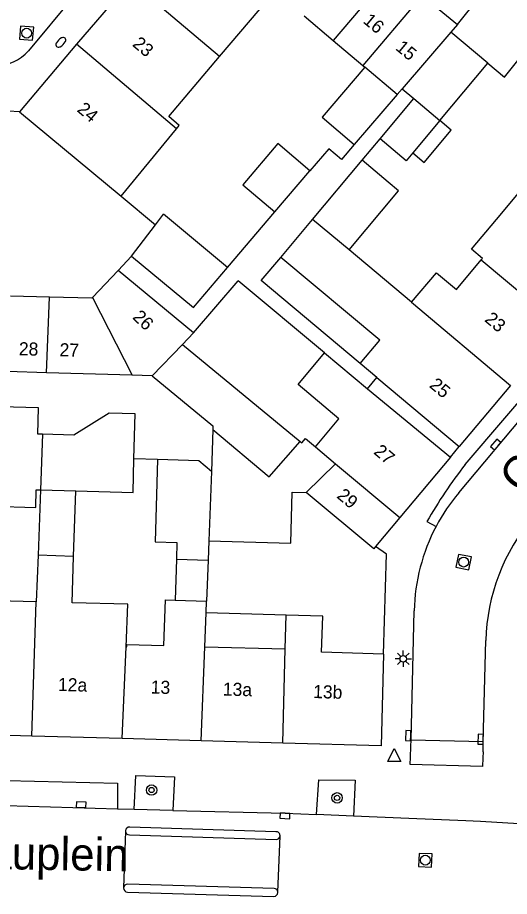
# Model space of a CAD drawing. Extents: x 132573 to 132944, y 398226 to 398676.
# Drawn here: x 132872.8 to 132910.4, y 398274.7 to 398341.8 of the extents above; entities that cross this region are included whole.
import ezdxf

# ---------------------------------------------------------------- set-up
doc = ezdxf.new("R2010")
doc.units = 0
for name, color, linetype in [('gg-afsc-erfafscheiding', 7, 'Continuous'), ('gg-afsc-muur', 7, 'Continuous'), ('gg-anno-huisnummerreeks BGT', 7, 'Continuous'), ('gg-anno-openbare ruimte label', 7, 'Continuous'), ('gg-bbg-bijgebouw', 7, 'Continuous'), ('gg-bbg-gedigitaliseerde bebouwing', 7, 'Continuous'), ('gg-bbg-gedigitaliseerde bebouwing onder overbouw', 7, 'Continuous'), ('gg-bbg-gedigitaliseerde bijgebouw', 7, 'Continuous'), ('gg-bbg-gedigitaliseerde overbouw', 7, 'Continuous'), ('gg-bbg-hoofdgebouw', 7, 'Continuous'), ('gg-bbg-luifel en loopbrug', 7, 'Continuous'), ('gg-bbg-pand overbouw', 7, 'Continuous'), ('gg-bbg-tussenscheiding', 7, 'Continuous'), ('gg-knt-verharding', 7, 'Continuous'), ('gg-knt-verharding nz', 7, 'Continuous'), ('gt-symb-boom', 7, 'Continuous'), ('gt-symb-brandkraan', 7, 'Continuous'), ('gt-symb-kolk', 7, 'Continuous'), ('gt-symb-lichtmast', 7, 'Continuous'), ('gt-symb-rioolschacht', 7, 'Continuous'), ('gt-symb-waterafsluiter', 7, 'Continuous')]:
    doc.layers.add(name, color=color, linetype=linetype)

msp = doc.modelspace()

# ---------------------------------------------------------------- linework, layer by layer
at = {"layer": 'gg-afsc-erfafscheiding'}
for p, q in [((132899.138, 398330.927), (132900.51, 398332.564)), ((132888.86, 398322.738), (132892.469, 398326.97)), ((132886.266, 398317.726), (132889.671, 398321.72)), ((132896.261, 398316.198), (132889.671, 398321.72)), ((132883.514, 398308.056), (132881.705, 398308.103))]:
    msp.add_line(p, q, dxfattribs=at)
for points in [[(132898.536, 398332.137), (132897.558, 398330.97), (132896.583, 398331.795), (132895.152, 398330.117)], [(132898.992, 398315.392), (132891.43, 398321.729), (132892.917, 398323.503)]]:
    msp.add_lwpolyline(points, dxfattribs=at)
at = {"layer": 'gg-afsc-muur'}
msp.add_line((132880.732, 398328.18), (132883.355, 398325.989), dxfattribs=at)
msp.add_lwpolyline([(132900.78, 398293.185), (132900.99, 398300.82), (132900.167, 398301.416)], dxfattribs=at)
at = {"layer": 'gg-bbg-bijgebouw'}
for p, q in [((132906.42, 398341.29), (132910.388, 398346.238)), ((132903.731, 398343.519), (132906.42, 398341.29)), ((132883.355, 398325.989), (132883.966, 398326.793)), ((132881.526, 398323.584), (132883.355, 398325.989)), ((132880.503, 398322.5), (132878.549, 398320.448)), ((132886.266, 398317.726), (132880.503, 398322.5)), ((132875.263, 398320.47), (132872.269, 398320.548)), ((132902.02, 398303.628), (132900.167, 398301.416)), ((132900.167, 398301.416), (132900.02, 398301.24))]:
    msp.add_line(p, q, dxfattribs=at)
msp.add_lwpolyline([(132878.549, 398320.448), (132878.489, 398320.385), (132875.263, 398320.47)], dxfattribs=at)
at = {"layer": 'gg-bbg-gedigitaliseerde bebouwing'}
for p, q in [((132888.246, 398338.849), (132892.476, 398343.845)), ((132884.952, 398333.331), (132885.164, 398333.59)), ((132880.732, 398328.18), (132884.952, 398333.331)), ((132909.405, 398326.405), (132911.337, 398328.711)), ((132892.917, 398323.503), (132895.351, 398326.407)), ((132902.912, 398320.07), (132898.136, 398324.072)), ((132900.479, 398317.166), (132892.917, 398323.503)), ((132898.992, 398315.392), (132900.479, 398317.166)), ((132896.261, 398316.198), (132899.536, 398313.454)), ((132900.265, 398314.324), (132898.992, 398315.392)), ((132895.577, 398309.027), (132897.37, 398311.167)), ((132874.392, 398300.75), (132874.234, 398297.191)), ((132877.095, 398300.661), (132874.392, 398300.75)), ((132874.234, 398297.191), (132867.226, 398297.386)), ((132884.866, 398297.314), (132887.25, 398297.248)), ((132887.216, 398296.355), (132887.25, 398297.248)), ((132887.117, 398293.758), (132887.216, 398296.355)), ((132893.255, 398293.592), (132893.324, 398296.168)), ((132887.117, 398293.758), (132893.255, 398293.592))]:
    msp.add_line(p, q, dxfattribs=at)
for points in [[(132885.164, 398333.59), (132884.366, 398334.265), (132888.246, 398338.849)], [(132908.23, 398323.307), (132908.33, 398323.426), (132907.495, 398324.126), (132909.405, 398326.405)], [(132902.912, 398320.07), (132904.806, 398322.33), (132906.337, 398321.047), (132908.23, 398323.307)], [(132897.37, 398311.167), (132894.242, 398313.788), (132896.261, 398316.198)], [(132881.104, 398293.735), (132881.241, 398296.997), (132876.977, 398297.101), (132877.095, 398300.661)], [(132883.984, 398293.843), (132884.117, 398297.335), (132884.866, 398297.314)], [(132881.104, 398293.735), (132881.151, 398293.734), (132881.156, 398293.919), (132883.984, 398293.843)]]:
    msp.add_lwpolyline(points, dxfattribs=at)
at = {"layer": 'gg-bbg-gedigitaliseerde bebouwing onder overbouw'}
for p, q in [((132900.265, 398314.324), (132906.562, 398309.046)), ((132899.536, 398313.454), (132905.882, 398308.235))]:
    msp.add_line(p, q, dxfattribs=at)
at = {"layer": 'gg-bbg-gedigitaliseerde bijgebouw'}
for p, q in [((132910.008, 398337.28), (132914.457, 398342.827)), ((132894.719, 398341.948), (132896.932, 398340.075)), ((132896.932, 398340.075), (132899.196, 398338.16)), ((132905.075, 398333.957), (132908.746, 398338.337)), ((132908.746, 398338.337), (132910.008, 398337.28)), ((132899.196, 398338.16), (132899.333, 398338.044)), ((132902.187, 398336.376), (132901.816, 398335.945)), ((132902.187, 398336.376), (132903.078, 398335.629)), ((132901.816, 398335.945), (132898.536, 398332.137)), ((132900.51, 398332.564), (132903.078, 398335.629)), ((132905.075, 398333.957), (132903, 398331.481)), ((132895.351, 398326.407), (132899.138, 398330.927)), ((132901.134, 398329.254), (132899.138, 398330.927)), ((132892.469, 398326.97), (132895.152, 398330.117)), ((132888.86, 398322.738), (132883.966, 398326.793)), ((132881.526, 398323.584), (132886.249, 398319.675)), ((132886.249, 398319.675), (132888.86, 398322.738)), ((132886.266, 398317.726), (132885.404, 398316.836)), ((132885.404, 398316.836), (132894.398, 398309.429)), ((132875.037, 398314.69), (132872.043, 398314.777)), ((132881.567, 398314.502), (132875.037, 398314.69)), ((132883.1, 398314.458), (132881.567, 398314.502)), ((132887.73, 398310.354), (132887.63, 398307.149)), ((132874.564, 398305.744), (132877.261, 398305.669)), ((132900.02, 398301.24), (132894.861, 398305.539)), ((132887.426, 398301.844), (132887.37, 398300.373)), ((132884.953, 398300.44), (132887.37, 398300.373))]:
    msp.add_line(p, q, dxfattribs=at)
for points in [[(132899.333, 398338.044), (132896.085, 398334.217), (132898.536, 398332.137)], [(132895.152, 398330.117), (132892.703, 398332.205), (132890.012, 398329.049), (132892.469, 398326.97)], [(132903, 398331.481), (132902.506, 398330.891), (132900.51, 398332.564)], [(132898.136, 398324.072), (132901.924, 398328.592), (132901.134, 398329.254)], [(132883.1, 398314.458), (132887.738, 398310.639), (132887.73, 398310.354)], [(132874.711, 398309.991), (132874.355, 398310.001), (132874.411, 398312.001), (132867.666, 398312.188)], [(132881.705, 398308.103), (132881.801, 398311.545), (132879.802, 398311.601), (132877.104, 398309.925), (132874.711, 398309.991)], [(132894.398, 398309.429), (132894.526, 398309.324), (132894.805, 398309.663), (132895.577, 398309.027)], [(132877.261, 398305.669), (132881.634, 398305.547), (132881.705, 398308.103)], [(132883.514, 398308.056), (132883.339, 398301.758), (132884.988, 398301.712), (132884.953, 398300.44)], [(132887.63, 398307.149), (132886.663, 398307.968), (132883.514, 398308.056)], [(132867.52, 398307.291), (132867.577, 398307.289), (132867.502, 398304.59), (132874.199, 398304.404), (132874.237, 398305.753), (132874.564, 398305.744)], [(132887.426, 398301.844), (132893.691, 398301.67), (132893.799, 398305.569), (132894.861, 398305.539)]]:
    msp.add_lwpolyline(points, dxfattribs=at)
at = {"layer": 'gg-bbg-gedigitaliseerde overbouw'}
msp.add_line((132899.536, 398313.454), (132900.265, 398314.324), dxfattribs=at)
at = {"layer": 'gg-bbg-hoofdgebouw'}
for p, q in [((132881.424, 398344.622), (132877.328, 398339.782)), ((132877.328, 398339.782), (132872.96, 398334.62)), ((132872.96, 398334.62), (132880.732, 398328.18)), ((132910.483, 398313.725), (132906.562, 398309.046)), ((132905.882, 398308.235), (132902.02, 398303.628)), ((132900.78, 398293.185), (132900.6, 398286.19)), ((132873.916, 398286.932), (132871.073, 398287.011)), ((132880.809, 398286.741), (132873.916, 398286.932)), ((132886.841, 398286.573), (132880.809, 398286.741)), ((132893.074, 398286.399), (132886.841, 398286.573)), ((132900.6, 398286.19), (132893.074, 398286.399))]:
    msp.add_line(p, q, dxfattribs=at)
msp.add_lwpolyline([(132900.78, 398293.185), (132896.031, 398293.33), (132896.139, 398296.082), (132893.324, 398296.168)], dxfattribs=at)
at = {"layer": 'gg-bbg-luifel en loopbrug'}
for p, q in [((132874.564, 398305.744), (132874.392, 398300.75)), ((132877.095, 398300.661), (132877.261, 398305.669)), ((132884.953, 398300.44), (132884.866, 398297.314)), ((132887.37, 398300.373), (132887.25, 398297.248)), ((132893.324, 398296.168), (132887.216, 398296.355))]:
    msp.add_line(p, q, dxfattribs=at)
msp.add_lwpolyline([(132903, 398331.481), (132903.865, 398330.757), (132905.94, 398333.233), (132905.075, 398333.957)], dxfattribs=at)
at = {"layer": 'gg-bbg-pand overbouw'}
msp.add_line((132905.882, 398308.235), (132906.562, 398309.046), dxfattribs=at)
at = {"layer": 'gg-bbg-tussenscheiding'}
for p, q in [((132901.448, 398345.411), (132896.932, 398340.075)), ((132888.246, 398338.849), (132881.424, 398344.622)), ((132903.731, 398343.519), (132899.196, 398338.16)), ((132906.42, 398341.29), (132905.918, 398340.707)), ((132905.918, 398340.707), (132902.187, 398336.376)), ((132908.746, 398338.337), (132905.918, 398340.707)), ((132884.952, 398333.331), (132877.328, 398339.782)), ((132901.816, 398335.945), (132899.333, 398338.044)), ((132903.078, 398335.629), (132905.075, 398333.957)), ((132898.136, 398324.072), (132895.351, 398326.407)), ((132908.23, 398323.307), (132914.27, 398318.244)), ((132875.037, 398314.69), (132875.263, 398320.47)), ((132878.549, 398320.448), (132881.567, 398314.502)), ((132902.912, 398320.07), (132910.483, 398313.725)), ((132883.1, 398314.458), (132885.404, 398316.836)), ((132874.711, 398309.991), (132874.564, 398305.744)), ((132895.577, 398309.027), (132897.113, 398307.74)), ((132894.861, 398305.539), (132897.113, 398307.74)), ((132897.113, 398307.74), (132902.02, 398303.628)), ((132887.63, 398307.149), (132887.426, 398301.844)), ((132873.916, 398286.932), (132874.234, 398297.191)), ((132880.809, 398286.741), (132881.104, 398293.735)), ((132886.841, 398286.573), (132887.117, 398293.758)), ((132893.074, 398286.399), (132893.255, 398293.592))]:
    msp.add_line(p, q, dxfattribs=at)
msp.add_lwpolyline([(132887.73, 398310.354), (132892.028, 398306.74), (132894.398, 398309.429)], dxfattribs=at)
at = {"layer": 'gg-knt-verharding'}
for p, q in [((132881.896, 398349.211), (132873.641, 398339.288)), ((132872.96, 398334.62), (132867.14, 398335.01)), ((132880.503, 398322.5), (132881.526, 398323.584)), ((132906.52, 398305.52), (132920.22, 398321.839)), ((132902.875, 398286.651), (132903.109, 398296.502)), ((132908.396, 398286.505), (132908.58, 398294.222)), ((132902.862, 398286.128), (132902.875, 398286.651)), ((132902.875, 398286.651), (132908.396, 398286.505)), ((132908.378, 398285.735), (132908.396, 398286.505)), ((132902.843, 398285.326), (132902.862, 398286.128)), ((132902.798, 398284.756), (132902.843, 398285.326)), ((132908.361, 398285.275), (132908.337, 398284.61)), ((132908.378, 398285.735), (132908.361, 398285.275)), ((132908.337, 398284.61), (132902.798, 398284.756)), ((132880.446, 398281.347), (132871.917, 398281.588)), ((132881.719, 398281.311), (132880.446, 398281.347)), ((132884.68, 398281.235), (132881.719, 398281.311)), ((132898.475, 398280.804), (132895.661, 398280.927)), ((132902.701, 398280.632), (132898.475, 398280.804)), ((132892.557, 398279.624), (132881.379, 398279.97)), ((132914.016, 398280.052), (132908.181, 398280.39)), ((132881.057, 398279.666), (132880.918, 398275.328)), ((132881.058, 398279.7), (132881.057, 398279.666)), ((132881.356, 398279.376), (132892.559, 398279.019)), ((132892.696, 398274.991), (132892.864, 398279.3)), ((132892.864, 398279.3), (132892.865, 398279.319)), ((132892.412, 398275.292), (132881.237, 398275.62)), ((132881.21, 398275.007), (132892.396, 398274.677)), ((132892.695, 398274.965), (132892.696, 398274.991))]:
    msp.add_line(p, q, dxfattribs=at)
for points in [[(132881.719, 398281.311), (132881.855, 398283.904), (132884.814, 398283.818), (132884.68, 398281.235)], [(132871.917, 398281.588), (132871.992, 398283.526), (132880.446, 398283.338), (132880.446, 398281.347)], [(132895.661, 398280.927), (132895.828, 398283.595), (132898.615, 398283.562), (132898.475, 398280.804)], [(132884.68, 398281.235), (132893.246, 398281.033), (132895.661, 398280.927)], [(132908.181, 398280.39), (132907.058, 398280.455), (132902.701, 398280.632)]]:
    msp.add_lwpolyline(points, dxfattribs=at)
for centre, radius, start, end in [((132871.199, 398341.418), 3.241, 268.22036, 318.90359), ((132917.651, 398296.157), 14.545, 139.93235, 152.16455), ((132923.867, 398293.772), 15.294, 140.00224, 178.31374), ((132917.653, 398296.154), 14.548, 152.1579, 178.63074), ((132881.355, 398279.673), 0.298, 85.36573, 174.77009), ((132881.354, 398279.673), 0.297, 181.37149, 270.37935), ((132892.561, 398279.32), 0.304, 359.7889, 90.7719), ((132892.562, 398279.322), 0.303, 269.45359, 355.85586), ((132881.227, 398275.311), 0.309, 88.09534, 176.84417), ((132881.225, 398275.314), 0.308, 177.44441, 267.13849), ((132892.387, 398274.984), 0.309, 1.25813, 85.41279), ((132892.389, 398274.983), 0.307, 271.30695, 356.54593)]:
    msp.add_arc(centre, radius, start, end, dxfattribs=at)
at = {"layer": 'gg-knt-verharding nz'}
msp.add_line((132904.081, 398303.322), (132904.789, 398302.949), dxfattribs=at)
msp.add_lwpolyline([(132907.015, 398307.688), (132919.585, 398322.372), (132920.22, 398321.839)], dxfattribs=at)
msp.add_arc((132937.461, 398284.059), 38.539, 142.18521, 150.01172, dxfattribs=at)
at = {"layer": 'gt-symb-boom'}
for centre, radius in [((132883.052, 398282.805), 0.4), ((132883.052, 398282.805), 0.2), ((132897.222, 398282.207), 0.4), ((132897.222, 398282.207), 0.2)]:
    msp.add_circle(centre, radius, dxfattribs=at)
at = {"layer": 'gt-symb-brandkraan'}
for centre, radius, start, end in [((132876.602, 398339.437), 0.938, 117.37866, 151.16272), ((132877.551, 398337.606), 3, 116.70376, 117.37866), ((132876.295, 398340.102), 0.206, 331.83762, 116.70376), ((132875.945, 398339.762), 0.206, 151.83761, 296.70375), ((132878.409, 398338.443), 3, 151.16272, 151.83761), ((132874.689, 398342.258), 3, 296.70375, 297.37864), ((132875.638, 398340.427), 0.938, 297.37864, 331.16274), ((132873.831, 398341.421), 3, 331.16274, 331.83762)]:
    msp.add_arc(centre, radius, start, end, dxfattribs=at)
at = {"layer": 'gt-symb-kolk'}
for points in [[(132909.5, 398309.073), (132909.741, 398309.36), (132909.435, 398309.617), (132908.953, 398309.043), (132909.259, 398308.786), (132909.5, 398309.073)], [(132902.856, 398286.952), (132902.87, 398287.327), (132902.471, 398287.342), (132902.442, 398286.592), (132902.842, 398286.577), (132902.856, 398286.952)], [(132908.392, 398286.68), (132908.402, 398287.055), (132908.002, 398287.065), (132907.982, 398286.316), (132908.382, 398286.305), (132908.392, 398286.68)], [(132877.666, 398281.48), (132878.041, 398281.468), (132878.054, 398281.867), (132877.304, 398281.892), (132877.291, 398281.492), (132877.666, 398281.48)], [(132893.246, 398281.033), (132892.871, 398281.05), (132892.854, 398280.65), (132893.603, 398280.617), (132893.621, 398281.016), (132893.246, 398281.033)]]:
    msp.add_lwpolyline(points, dxfattribs=at)
at = {"layer": 'gt-symb-lichtmast'}
for p, q in [((132902.106, 398293.01), (132901.841, 398293.275)), ((132902.283, 398293.083), (132902.283, 398293.458)), ((132902.46, 398293.01), (132902.725, 398293.275)), ((132902.033, 398292.833), (132901.658, 398292.833)), ((132902.106, 398292.656), (132901.841, 398292.391)), ((132902.283, 398292.583), (132902.283, 398292.208)), ((132902.725, 398292.391), (132902.46, 398292.656)), ((132902.533, 398292.833), (132902.908, 398292.833))]:
    msp.add_line(p, q, dxfattribs=at)
msp.add_circle((132902.283, 398292.833), 0.25, dxfattribs=at)
at = {"layer": 'gt-symb-rioolschacht'}
for points in [[(132874.047, 398341.092), (132873.05, 398341.173), (132872.969, 398340.176), (132873.966, 398340.095)], [(132906.498, 398300.807), (132906.304, 398299.825), (132907.286, 398299.631), (132907.48, 398300.613)], [(132903.445, 398276.97), (132904.444, 398276.925), (132904.489, 398277.924), (132903.49, 398277.969)]]:
    msp.add_lwpolyline(points, close=True, dxfattribs=at)
for centre in [(132873.508, 398340.634), (132906.892, 398300.219), (132903.967, 398277.447)]:
    msp.add_circle(centre, 0.375, dxfattribs=at)
at = {"layer": 'gt-symb-waterafsluiter'}
for p, q in [((132901.09, 398284.973), (132901.59, 398285.973)), ((132901.59, 398285.973), (132902.09, 398284.973)), ((132902.09, 398284.973), (132901.09, 398284.973))]:
    msp.add_line(p, q, dxfattribs=at)

# ---------------------------------------------------------------- texts
at = {"layer": 'gg-anno-huisnummerreeks BGT'}
for s, rotation, p in [('16', 320.4, (132899.144, 398341.475)), ('23', 319.7, (132881.526, 398339.704)), ('15', 320.3, (132901.628, 398339.418)), ('24', 319.7, (132877.296, 398334.701)), ('26', 316.4, (132881.538, 398318.868)), ('23', 320.1, (132908.43, 398318.664)), ('28', 358.5, (132872.903, 398316.03)), ('27', 358.5, (132876.013, 398315.949)), ('25', 320.1, (132904.21, 398313.632)), ('27', 320.1, (132899.955, 398308.551)), ('29', 320, (132897.135, 398305.187)), ('12a', 358.4, (132875.892, 398290.379)), ('13', 358.4, (132882.978, 398290.182)), ('13a', 358.4, (132888.488, 398290.029)), ('13b', 358.4, (132895.385, 398289.836))]:
    msp.add_text(s, height=1, rotation=rotation, dxfattribs=at).set_placement(p)
at = {"layer": 'gg-anno-openbare ruimte label'}
for s, rotation, p in [('Graaf Arnoldstraat', 50.2, (132911.342, 398305.3)), ('Nassauplein', 359, (132862.882, 398276.915))]:
    msp.add_text(s, height=2.5, rotation=rotation, dxfattribs=at).set_placement(p)

doc.saveas('drawing.dxf')
